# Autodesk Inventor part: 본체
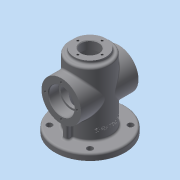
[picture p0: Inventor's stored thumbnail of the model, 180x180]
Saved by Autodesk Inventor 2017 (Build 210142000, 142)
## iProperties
Created: 2020-05
Part Number: 본체
Material: 알루미늄 6061
Document SubType Name: Modeling
Designer: mduedu
Density: 2.71 g/cm^3
Appearance: 기본값
Mass: 777.255 g
Surface Area: 687.925 cm^2
Volume: 286.81 cm^3
Author: mduedu
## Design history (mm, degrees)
sketch "스케치1"
  geometry: C1 r 32 at (0, 0); 1 further point
  constraints: 1 centre point, 1 coincident
  dimensions: "d0" = 64 diameter of C1
extrude "돌출1" new body sketch "스케치1" distance "d1" = 110; taper "d2" = 0 deg
feature "쉘1" dims "d3" = 8
fillet "모깎기1" dims "d4" = 3
fillet "모깎기2" dims "d5" = 3
sketch "스케치2"
  geometry: C1 r 25 at (0, 0); 1 further point
  constraints: 1 centre point, 1 coincident
  dimensions: "d6" = 50 diameter of C1
extrude "돌출2" join sketch "스케치2" distance "d7" = 5; taper "d8" = 0 deg
sketch "스케치3"
  geometry: C1 r 14 at (0, 0); 1 further point
  constraints: 1 centre point, 1 coincident
  dimensions: "d9" = 28 diameter of C1
extrude "돌출3" cut sketch "스케치3" stored distance "d10" = 5; taper "d11" = 0 deg
fillet "모깎기3" dims "d12" = 3
sketch "스케치4"
  geometry: C1 r 32 at (0, 0) reference; C2 r 55 at (0, 0); 1 further point
  constraints: 1 centre point, 1 coincident
  dimensions: "d13" = 110 diameter of C2
extrude "돌출4" join sketch "스케치4" distance "d14" = 10; taper "d15" = 0 deg
sketch "스케치5"
  geometry: L1 (0, 0)-(-31.82, 31.82); L2 (0, 0)-(-45, 0); A1 r 45 centre (0, 0) between (-31.82, 31.82) and (-45, 0); 1 further point
  constraints: 4 end point, 2 point on circle, 1 centre point, 1 coincident, 1 horizontal
  dimensions: "d16" = 90 diameter of A1; "d71" = 45 deg angle of L1 L2
hole "구멍1" sketch "스케치5" at (-31.82, 31.82) diameter "d17" = 9; stored, may be unused: countersink angle "d21" = 90 deg, drill point angle "d23" = 118 deg; dims "d18" = 6, "d19" = 4, "d20" = 2, "d22" = 8
fillet "모깎기4" dims "d27" = 3
node "작업 평면1"
sketch "스케치6"
  geometry: L1 (0, 55)-(0, -55) reference; C1 r 31 at (-65, 0); 2 further points
  constraints: 1 centre point, 1 horizontal alignment, 1 midpoint
  dimensions: "d31" = 62 diameter of C1; "d32" = 65 distance from line of C1.centre L1
extrude "돌출5" join sketch "스케치6" stored distance "d33" = 10; taper "d34" = 0 deg
fillet "모깎기5" dims "d35" = 3
sketch "스케치7"
  geometry: C1 r 31 at (0, 0) reference; C2 r 20 at (0, 0); 1 further point
  constraints: 1 centre point, 1 coincident
  dimensions: "d36" = 40 diameter of C2
extrude "돌출6" cut sketch "스케치7" distance "d37" = 16; taper "d38" = 0 deg
sketch "스케치8"
  geometry: C1 r 20 at (0, 0) reference; C2 r 17 at (0, 0); 1 further point
  constraints: 1 centre point, 1 coincident
  dimensions: "d39" = 34 diameter of C2
extrude "돌출7" cut sketch "스케치8" stored distance "d40" = 15; taper "d41" = 0 deg
fillet "모깎기6" dims "d42" = 0.3
chamfer "모따기1" distance "d43" = 1; stored, may be unused: second distance "d44" = 2, angle "d45" = 45 deg
chamfer "모따기2" distance "d46" = 1; stored, may be unused: second distance "d47" = 2, angle "d48" = 45 deg
sketch "스케치9" dims "d49" = 50
  geometry: C1 r 31 at (0, 0) reference; 3 further points
  constraints: 2 vertical alignment, 1 coincident, 2 other
hole "구멍2" sketch "스케치9" at (0, 25) diameter "d50" = 3.242; stored, may be unused: countersink angle "d54" = 90 deg, drill point angle "d56" = 118 deg; dims "d51" = 7, "d52" = 4, "d53" = 2, "d55" = 9
sketch "스케치10" dims "d60" = 38
  geometry: 3 further points
  constraints: 2 vertical alignment, 1 coincident, 2 other
hole "구멍3" sketch "스케치10" at (0, 19) diameter "d61" = 3.242; stored, may be unused: countersink angle "d65" = 90 deg, drill point angle "d67" = 118 deg; dims "d62" = 8, "d63" = 4, "d64" = 2, "d66" = 10
sketch "스케치11"
  geometry: L1 (32, 31)-(32, 13) reference; L2 (35, 10)-(52, 10) reference; L3 (55, 7)-(55, 0) reference; L4 (55, 0)-(24, 0) reference; L5 (24, 0)-(24, 48) reference; L6 (24, 48)-(29, 48) reference; L7 (29, 48)-(29, 45.3) reference; L8 (29.3, 45)-(44, 45) reference; L9 (44, 45)-(45, 44) reference; L10 (45, 44)-(45, 41.621) reference; L11 (45, 41.621)-(36, 41.621) reference; L12 (36, 41.621)-(35.026, 40) reference; L13 (35.026, 40)-(36, 38.379) reference; L14 (36, 38.379)-(45, 38.379) reference; L15 (45, 38.379)-(45, 34) reference; L16 (45, 34)-(35, 34) reference; L17 (-32, 13)-(-32, 31) reference; L18 (-35, 34)-(-45, 34) reference; L19 (-45, 34)-(-45, 38.379) reference; L20 (-45, 38.379)-(-36, 38.379) reference; L21 (-36, 38.379)-(-35.026, 40) reference; L22 (-35.026, 40)-(-36, 41.621) reference; L23 (-36, 41.621)-(-45, 41.621) reference; L24 (-45, 41.621)-(-45, 44) reference; L25 (-45, 44)-(-44, 45) reference; L26 (-44, 45)-(-29.3, 45) reference; L27 (-29, 45.3)-(-29, 48) reference; L28 (-29, 48)-(-24, 48) reference; L29 (-24, 48)-(-24, 0) reference; L30 (-24, 0)-(-55, 0) reference; L31 (-55, 0)-(-55, 7) reference; L32 (-52, 10)-(-35, 10) reference; L33 (-25, 113)-(-25, 115) reference; L34 (-25, 115)-(-20.621, 115) reference; L35 (-20.621, 115)-(-20.621, 105) reference; L36 (-20.621, 105)-(-19, 104.026) reference; L37 (-19, 104.026)-(-17.379, 105) reference; L38 (-17.379, 105)-(-17.379, 115) reference; L39 (-17.379, 115)-(-15, 115) reference; L40 (-15, 115)-(-14, 114) reference; L41 (-14, 114)-(-14, 102) reference; L42 (-14, 102)-(-21, 102) reference; L43 (-24, 99)-(-24, 82) reference; L44 (-24, 82)-(-29, 82) reference; L45 (-29, 82)-(-29, 84.7) reference; L46 (-29.3, 85)-(-44, 85) reference; L47 (-44, 85)-(-45, 86) reference; L48 (-45, 86)-(-45, 88.379) reference; L49 (-45, 88.379)-(-36, 88.379) reference; L50 (-36, 88.379)-(-35.026, 90) reference; L51 (-35.026, 90)-(-36, 91.621) reference; L52 (-36, 91.621)-(-45, 91.621) reference; L53 (-45, 91.621)-(-45, 96) reference; L54 (-45, 96)-(-35, 96) reference; L55 (-32, 99)-(-32, 107) reference; L56 (-29, 110)-(-28, 110) reference; L57 (28, 110)-(29, 110) reference; L58 (32, 107)-(32, 99) reference; L59 (35, 96)-(45, 96) reference; L60 (45, 96)-(45, 91.621) reference; L61 (45, 91.621)-(36, 91.621) reference; L62 (36, 91.621)-(35.026, 90) reference; L63 (35.026, 90)-(36, 88.379) reference; L64 (36, 88.379)-(45, 88.379) reference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; A1 r 3 centre (35, 13) between (32, 13) and (35, 10) reference; A2 r 3 centre (52, 7) between (55, 7) and (52, 10) reference; A3 r 0.3 centre (29.3, 45.3) between (29, 45.3) and (29.3, 45) reference; A4 r 0.3 centre (-29.3, 45.3) between (-29.3, 45) and (-29, 45.3) reference; A5 r 3 centre (-52, 7) between (-52, 10) and (-55, 7) reference; A6 r 3 centre (-35, 13) between (-35, 10) and (-32, 13) reference; A7 r 3 centre (-28, 113) between (-28, 110) and (-25, 113) reference; A8 r 3 centre (-21, 99) between (-21, 102) and (-24, 99) reference; A9 r 0.3 centre (-29.3, 84.7) between (-29, 84.7) and (-29.3, 85) reference; A10 r 3 centre (-29, 107) between (-29, 110) and (-32, 107) reference; A11 r 3 centre (28, 113) between (25, 113) and (28, 110) reference; A12 r 3 centre (29, 107) between (32, 107) and (29, 110) reference; A13 r 0.3 centre (29.3, 84.7) between (29.3, 85) and (29, 84.7) reference; A14 r 3 centre (21, 99) between (24, 99) and (21, 102) reference; 1 further point
  constraints: 2 end point, 1 midpoint, 1 perpendicular, 1 point on line, 4 other
  dimensions: "d73" = 5 distance between parallel lines of L81 L19
feature "리브1" sketch "스케치11" dims "d74" = 1, "d75" = 8, "d76" = 0, "d77" = 0, "d78" = 1, "d79" = 1
fillet "모깎기7" dims "d80" = 3
fillet "모깎기8" dims "d81" = 3
node "작업 평면2"
sketch "스케치12"
  geometry: 2 further points
  constraints: 1 vertical alignment, 1 other
  dimensions: "d83" = 25 distance of point (0, 25) point (0, 0)
feature "엠보싱1" sketch "스케치12" dims "d0" = 64, "d84" = 0.5, "d85" = 0
node "솔리드1"
pattern_circular "원형 패턴1" dims angle "d25" = 360 deg
mirror "대칭1"
mirror "대칭2"
pattern_circular "원형 패턴2" dims angle "d58" = 360 deg
mirror "대칭3"
pattern_circular "원형 패턴3" dims angle "d69" = 360 deg
mirror "대칭4"
node "투영된 루프1"
node "투영된 루프2"
node "절단 모서리 투영1"
other parameters: "d30" = -45
